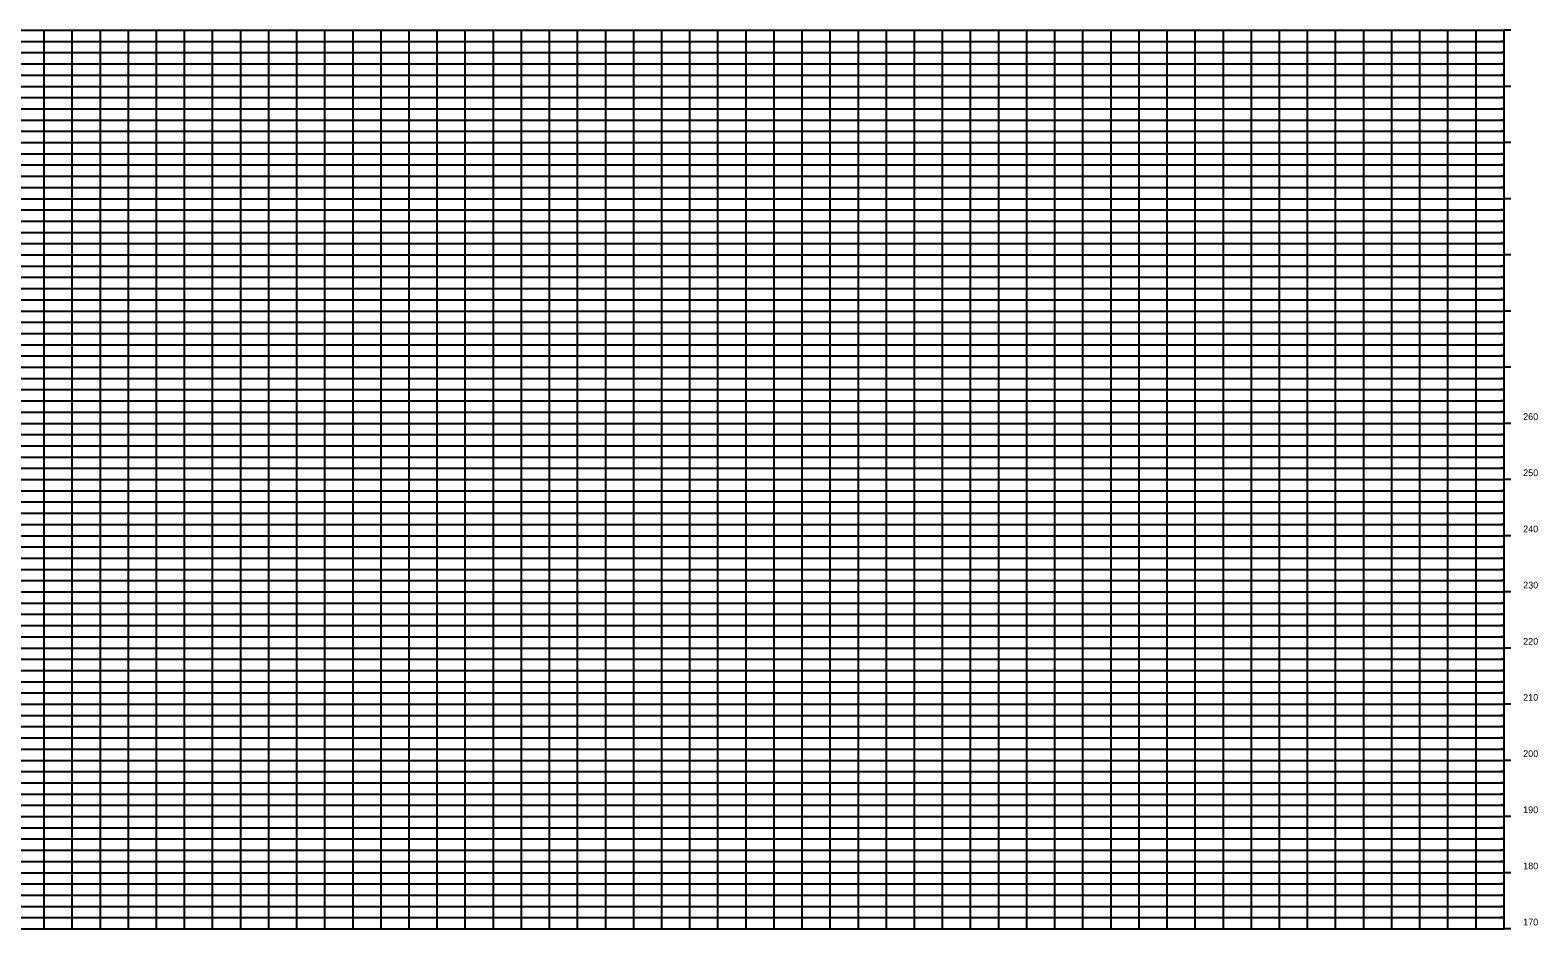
# Model space of a CAD drawing. Extents: x 1384498 to 1391279, y 1965973 to 1976560.
# Drawn here: x 1389536 to 1390879, y 1967223 to 1968023 of the extents above; entities that cross this region are included whole.
import ezdxf

# ---------------------------------------------------------------- set-up
doc = ezdxf.new("R2010")
doc.units = 0
for name, color, linetype in [('R_Axis_Annotation', 7, 'Continuous'), ('R_Grid', 7, 'Continuous'), ('R_Grid Annot', 7, 'Continuous'), ('R_Grid_Minor', 7, 'Continuous')]:
    doc.layers.add(name, color=color, linetype=linetype)

msp = doc.modelspace()

# ---------------------------------------------------------------- linework, layer by layer
at = {"layer": 'R_Grid'}
for p, q in [((1388248.8, 1968023.1), (1390848.8, 1968023.1)), ((1388248.8, 1968023.1), (1390848.8, 1968023.1)), ((1389548.8, 1967223.1), (1389548.8, 1968023.1)), ((1389648.8, 1967223.1), (1389648.8, 1968023.1)), ((1389748.8, 1967223.1), (1389748.8, 1968023.1)), ((1389848.8, 1967223.1), (1389848.8, 1968023.1)), ((1389948.8, 1967223.1), (1389948.8, 1968023.1)), ((1390048.8, 1967223.1), (1390048.8, 1968023.1)), ((1390148.8, 1967223.1), (1390148.8, 1968023.1)), ((1390248.8, 1967223.1), (1390248.8, 1968023.1)), ((1390348.8, 1967223.1), (1390348.8, 1968023.1)), ((1390448.8, 1967223.1), (1390448.8, 1968023.1)), ((1390548.8, 1967223.1), (1390548.8, 1968023.1)), ((1390648.8, 1967223.1), (1390648.8, 1968023.1)), ((1390748.8, 1967223.1), (1390748.8, 1968023.1)), ((1390848.8, 1967223.1), (1390848.8, 1968023.1)), ((1388248.8, 1967973.1), (1390848.8, 1967973.1)), ((1388248.8, 1967923.1), (1390848.8, 1967923.1)), ((1388248.8, 1967873.1), (1390848.8, 1967873.1)), ((1388248.8, 1967823.1), (1390848.8, 1967823.1)), ((1388248.8, 1967773.1), (1390848.8, 1967773.1)), ((1388248.8, 1967723.1), (1390848.8, 1967723.1)), ((1388248.8, 1967673.1), (1390848.8, 1967673.1)), ((1388248.8, 1967623.1), (1390848.8, 1967623.1)), ((1388248.8, 1967573.1), (1390848.8, 1967573.1)), ((1388248.8, 1967523.1), (1390848.8, 1967523.1)), ((1388248.8, 1967473.1), (1390848.8, 1967473.1)), ((1388248.8, 1967423.1), (1390848.8, 1967423.1)), ((1388248.8, 1967373.1), (1390848.8, 1967373.1)), ((1388248.8, 1967323.1), (1390848.8, 1967323.1)), ((1388248.8, 1967273.1), (1390848.8, 1967273.1)), ((1388248.8, 1967223.1), (1390848.8, 1967223.1))]:
    msp.add_line(p, q, dxfattribs=at)
at = {"layer": 'R_Grid Annot'}
for p, q in [((1390848.8, 1968013.1), (1390845.8, 1968013.1)), ((1390854.8, 1968023.1), (1390848.8, 1968023.1)), ((1390854.8, 1968023.1), (1390848.8, 1968023.1)), ((1390848.8, 1968003.1), (1390845.8, 1968003.1)), ((1390848.8, 1967993.1), (1390845.8, 1967993.1)), ((1390848.8, 1967983.1), (1390845.8, 1967983.1)), ((1390854.8, 1967973.1), (1390848.8, 1967973.1)), ((1390848.8, 1967963.1), (1390845.8, 1967963.1)), ((1390848.8, 1967953.1), (1390845.8, 1967953.1)), ((1390848.8, 1967943.1), (1390845.8, 1967943.1)), ((1390848.8, 1967933.1), (1390845.8, 1967933.1)), ((1390854.8, 1967923.1), (1390848.8, 1967923.1)), ((1390848.8, 1967913.1), (1390845.8, 1967913.1)), ((1390848.8, 1967903.1), (1390845.8, 1967903.1)), ((1390848.8, 1967893.1), (1390845.8, 1967893.1)), ((1390848.8, 1967883.1), (1390845.8, 1967883.1)), ((1390854.8, 1967873.1), (1390848.8, 1967873.1)), ((1390848.8, 1967863.1), (1390845.8, 1967863.1)), ((1390848.8, 1967853.1), (1390845.8, 1967853.1)), ((1390848.8, 1967843.1), (1390845.8, 1967843.1)), ((1390848.8, 1967833.1), (1390845.8, 1967833.1)), ((1390848.8, 1967813.1), (1390845.8, 1967813.1)), ((1390854.8, 1967823.1), (1390848.8, 1967823.1)), ((1390848.8, 1967803.1), (1390845.8, 1967803.1)), ((1390848.8, 1967793.1), (1390845.8, 1967793.1)), ((1390848.8, 1967783.1), (1390845.8, 1967783.1)), ((1390854.8, 1967773.1), (1390848.8, 1967773.1)), ((1390848.8, 1967763.1), (1390845.8, 1967763.1)), ((1390848.8, 1967753.1), (1390845.8, 1967753.1)), ((1390848.8, 1967743.1), (1390845.8, 1967743.1)), ((1390848.8, 1967733.1), (1390845.8, 1967733.1)), ((1390854.8, 1967723.1), (1390848.8, 1967723.1)), ((1390848.8, 1967713.1), (1390845.8, 1967713.1)), ((1390848.8, 1967703.1), (1390845.8, 1967703.1)), ((1390848.8, 1967693.1), (1390845.8, 1967693.1)), ((1390848.8, 1967683.1), (1390845.8, 1967683.1)), ((1390848.8, 1967663.1), (1390845.8, 1967663.1)), ((1390854.8, 1967673.1), (1390848.8, 1967673.1)), ((1390848.8, 1967653.1), (1390845.8, 1967653.1)), ((1390848.8, 1967643.1), (1390845.8, 1967643.1)), ((1390848.8, 1967633.1), (1390845.8, 1967633.1)), ((1390854.8, 1967623.1), (1390848.8, 1967623.1)), ((1390848.8, 1967613.1), (1390845.8, 1967613.1)), ((1390848.8, 1967603.1), (1390845.8, 1967603.1)), ((1390848.8, 1967593.1), (1390845.8, 1967593.1)), ((1390848.8, 1967583.1), (1390845.8, 1967583.1)), ((1390854.8, 1967573.1), (1390848.8, 1967573.1)), ((1390848.8, 1967563.1), (1390845.8, 1967563.1)), ((1390848.8, 1967553.1), (1390845.8, 1967553.1)), ((1390848.8, 1967543.1), (1390845.8, 1967543.1)), ((1390848.8, 1967533.1), (1390845.8, 1967533.1)), ((1390854.8, 1967523.1), (1390848.8, 1967523.1)), ((1390848.8, 1967513.1), (1390845.8, 1967513.1)), ((1390848.8, 1967503.1), (1390845.8, 1967503.1)), ((1390848.8, 1967493.1), (1390845.8, 1967493.1)), ((1390848.8, 1967483.1), (1390845.8, 1967483.1)), ((1390848.8, 1967463.1), (1390845.8, 1967463.1)), ((1390854.8, 1967473.1), (1390848.8, 1967473.1)), ((1390848.8, 1967453.1), (1390845.8, 1967453.1)), ((1390848.8, 1967443.1), (1390845.8, 1967443.1)), ((1390848.8, 1967433.1), (1390845.8, 1967433.1)), ((1390854.8, 1967423.1), (1390848.8, 1967423.1)), ((1390848.8, 1967413.1), (1390845.8, 1967413.1)), ((1390848.8, 1967403.1), (1390845.8, 1967403.1)), ((1390848.8, 1967393.1), (1390845.8, 1967393.1)), ((1390848.8, 1967383.1), (1390845.8, 1967383.1)), ((1390854.8, 1967373.1), (1390848.8, 1967373.1)), ((1390848.8, 1967363.1), (1390845.8, 1967363.1)), ((1390848.8, 1967353.1), (1390845.8, 1967353.1)), ((1390848.8, 1967343.1), (1390845.8, 1967343.1)), ((1390848.8, 1967333.1), (1390845.8, 1967333.1)), ((1390854.8, 1967323.1), (1390848.8, 1967323.1)), ((1390848.8, 1967313.1), (1390845.8, 1967313.1)), ((1390848.8, 1967303.1), (1390845.8, 1967303.1)), ((1390848.8, 1967293.1), (1390845.8, 1967293.1)), ((1390848.8, 1967283.1), (1390845.8, 1967283.1)), ((1390848.8, 1967263.1), (1390845.8, 1967263.1)), ((1390854.8, 1967273.1), (1390848.8, 1967273.1)), ((1390848.8, 1967253.1), (1390845.8, 1967253.1)), ((1390848.8, 1967243.1), (1390845.8, 1967243.1)), ((1390848.8, 1967233.1), (1390845.8, 1967233.1)), ((1390854.8, 1967223.1), (1390848.8, 1967223.1))]:
    msp.add_line(p, q, dxfattribs=at)
at = {"layer": 'R_Grid_Minor'}
for p, q in [((1388248.8, 1968013.1), (1390848.8, 1968013.1)), ((1389573.8, 1967223.1), (1389573.8, 1968023.1)), ((1389598.8, 1967223.1), (1389598.8, 1968023.1)), ((1389623.8, 1967223.1), (1389623.8, 1968023.1)), ((1389673.8, 1967223.1), (1389673.8, 1968023.1)), ((1389698.8, 1967223.1), (1389698.8, 1968023.1)), ((1389723.8, 1967223.1), (1389723.8, 1968023.1)), ((1389773.8, 1967223.1), (1389773.8, 1968023.1)), ((1389798.8, 1967223.1), (1389798.8, 1968023.1)), ((1389823.8, 1967223.1), (1389823.8, 1968023.1)), ((1389873.8, 1967223.1), (1389873.8, 1968023.1)), ((1389898.8, 1967223.1), (1389898.8, 1968023.1)), ((1389923.8, 1967223.1), (1389923.8, 1968023.1)), ((1389973.8, 1967223.1), (1389973.8, 1968023.1)), ((1389998.8, 1967223.1), (1389998.8, 1968023.1)), ((1390023.8, 1967223.1), (1390023.8, 1968023.1)), ((1390073.8, 1967223.1), (1390073.8, 1968023.1)), ((1390098.8, 1967223.1), (1390098.8, 1968023.1)), ((1390123.8, 1967223.1), (1390123.8, 1968023.1)), ((1390173.8, 1967223.1), (1390173.8, 1968023.1)), ((1390198.8, 1967223.1), (1390198.8, 1968023.1)), ((1390223.8, 1967223.1), (1390223.8, 1968023.1)), ((1390273.8, 1967223.1), (1390273.8, 1968023.1)), ((1390298.8, 1967223.1), (1390298.8, 1968023.1)), ((1390323.8, 1967223.1), (1390323.8, 1968023.1)), ((1390373.8, 1967223.1), (1390373.8, 1968023.1)), ((1390398.8, 1967223.1), (1390398.8, 1968023.1)), ((1390423.8, 1967223.1), (1390423.8, 1968023.1)), ((1390473.8, 1967223.1), (1390473.8, 1968023.1)), ((1390498.8, 1967223.1), (1390498.8, 1968023.1)), ((1390523.8, 1967223.1), (1390523.8, 1968023.1)), ((1390573.8, 1967223.1), (1390573.8, 1968023.1)), ((1390598.8, 1967223.1), (1390598.8, 1968023.1)), ((1390623.8, 1967223.1), (1390623.8, 1968023.1)), ((1390673.8, 1967223.1), (1390673.8, 1968023.1)), ((1390698.8, 1967223.1), (1390698.8, 1968023.1)), ((1390723.8, 1967223.1), (1390723.8, 1968023.1)), ((1390773.8, 1967223.1), (1390773.8, 1968023.1)), ((1390798.8, 1967223.1), (1390798.8, 1968023.1)), ((1390823.8, 1967223.1), (1390823.8, 1968023.1)), ((1388248.8, 1968003.1), (1390848.8, 1968003.1)), ((1388248.8, 1967993.1), (1390848.8, 1967993.1)), ((1388248.8, 1967983.1), (1390848.8, 1967983.1)), ((1388248.8, 1967963.1), (1390848.8, 1967963.1)), ((1388248.8, 1967953.1), (1390848.8, 1967953.1)), ((1388248.8, 1967943.1), (1390848.8, 1967943.1)), ((1388248.8, 1967933.1), (1390848.8, 1967933.1)), ((1388248.8, 1967913.1), (1390848.8, 1967913.1)), ((1388248.8, 1967903.1), (1390848.8, 1967903.1)), ((1388248.8, 1967893.1), (1390848.8, 1967893.1)), ((1388248.8, 1967883.1), (1390848.8, 1967883.1)), ((1388248.8, 1967863.1), (1390848.8, 1967863.1)), ((1388248.8, 1967853.1), (1390848.8, 1967853.1)), ((1388248.8, 1967843.1), (1390848.8, 1967843.1)), ((1388248.8, 1967833.1), (1390848.8, 1967833.1)), ((1388248.8, 1967813.1), (1390848.8, 1967813.1)), ((1388248.8, 1967803.1), (1390848.8, 1967803.1)), ((1388248.8, 1967793.1), (1390848.8, 1967793.1)), ((1388248.8, 1967783.1), (1390848.8, 1967783.1)), ((1388248.8, 1967763.1), (1390848.8, 1967763.1)), ((1388248.8, 1967753.1), (1390848.8, 1967753.1)), ((1388248.8, 1967743.1), (1390848.8, 1967743.1)), ((1388248.8, 1967733.1), (1390848.8, 1967733.1)), ((1388248.8, 1967713.1), (1390848.8, 1967713.1)), ((1388248.8, 1967703.1), (1390848.8, 1967703.1)), ((1388248.8, 1967693.1), (1390848.8, 1967693.1)), ((1388248.8, 1967683.1), (1390848.8, 1967683.1)), ((1388248.8, 1967663.1), (1390848.8, 1967663.1)), ((1388248.8, 1967653.1), (1390848.8, 1967653.1)), ((1388248.8, 1967643.1), (1390848.8, 1967643.1)), ((1388248.8, 1967633.1), (1390848.8, 1967633.1)), ((1388248.8, 1967613.1), (1390848.8, 1967613.1)), ((1388248.8, 1967603.1), (1390848.8, 1967603.1)), ((1388248.8, 1967593.1), (1390848.8, 1967593.1)), ((1388248.8, 1967583.1), (1390848.8, 1967583.1)), ((1388248.8, 1967563.1), (1390848.8, 1967563.1)), ((1388248.8, 1967553.1), (1390848.8, 1967553.1)), ((1388248.8, 1967543.1), (1390848.8, 1967543.1)), ((1388248.8, 1967533.1), (1390848.8, 1967533.1)), ((1388248.8, 1967513.1), (1390848.8, 1967513.1)), ((1388248.8, 1967503.1), (1390848.8, 1967503.1)), ((1388248.8, 1967493.1), (1390848.8, 1967493.1)), ((1388248.8, 1967483.1), (1390848.8, 1967483.1)), ((1388248.8, 1967463.1), (1390848.8, 1967463.1)), ((1388248.8, 1967453.1), (1390848.8, 1967453.1)), ((1388248.8, 1967443.1), (1390848.8, 1967443.1)), ((1388248.8, 1967433.1), (1390848.8, 1967433.1)), ((1388248.8, 1967413.1), (1390848.8, 1967413.1)), ((1388248.8, 1967403.1), (1390848.8, 1967403.1)), ((1388248.8, 1967393.1), (1390848.8, 1967393.1)), ((1388248.8, 1967383.1), (1390848.8, 1967383.1)), ((1388248.8, 1967363.1), (1390848.8, 1967363.1)), ((1388248.8, 1967353.1), (1390848.8, 1967353.1)), ((1388248.8, 1967343.1), (1390848.8, 1967343.1)), ((1388248.8, 1967333.1), (1390848.8, 1967333.1)), ((1388248.8, 1967313.1), (1390848.8, 1967313.1)), ((1388248.8, 1967303.1), (1390848.8, 1967303.1)), ((1388248.8, 1967293.1), (1390848.8, 1967293.1)), ((1388248.8, 1967283.1), (1390848.8, 1967283.1)), ((1388248.8, 1967263.1), (1390848.8, 1967263.1)), ((1388248.8, 1967253.1), (1390848.8, 1967253.1)), ((1388248.8, 1967243.1), (1390848.8, 1967243.1)), ((1388248.8, 1967233.1), (1390848.8, 1967233.1))]:
    msp.add_line(p, q, dxfattribs=at)

# ---------------------------------------------------------------- texts
at = {"layer": 'R_Axis_Annotation'}
for s, p in [('260', (1390865.8, 1967676.1)), ('250', (1390865.8, 1967626.1)), ('240', (1390865.8, 1967576.1)), ('230', (1390865.8, 1967526.1)), ('220', (1390865.8, 1967476.1)), ('210', (1390865.8, 1967426.1)), ('200', (1390865.8, 1967376.1)), ('190', (1390865.8, 1967326.1)), ('180', (1390865.8, 1967276.1)), ('170', (1390865.8, 1967226.1))]:
    msp.add_text(s, height=6, dxfattribs=at).set_placement(p)

doc.saveas('drawing.dxf')
